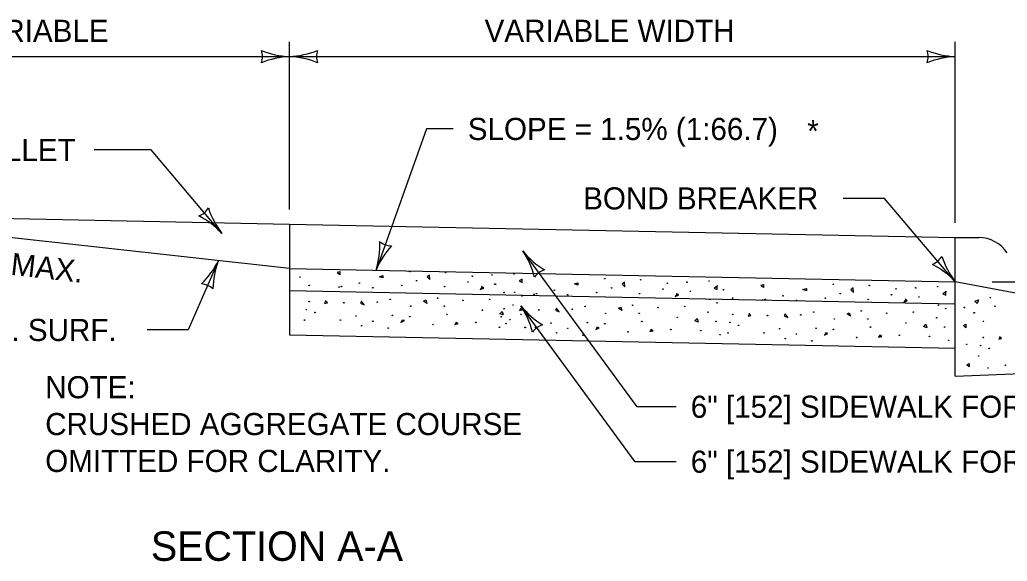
# Model space of a CAD drawing. Extents: x 49987.9 to 50021, y 49987.6 to 50011.4.
# Drawn here: x 50004.279 to 50006.956, y 50005.135 to 50006.604 of the extents above; entities that cross this region are included whole.
import ezdxf

# ---------------------------------------------------------------- set-up
doc = ezdxf.new("R2010")
doc.units = 0
for name, color, linetype in [('Level 1', 7, 'Continuous'), ('Level 2', 7, 'Continuous'), ('Level 3', 7, 'Continuous'), ('Level 4', 7, 'Continuous')]:
    doc.layers.add(name, color=color, linetype=linetype)

msp = doc.modelspace()

# ---------------------------------------------------------------- linework, layer by layer
at = {"layer": 'Level 1'}
for p, q in [((50005.0099, 50005.9293), (50002.004, 50006.2599)), ((50003.6615, 50006.0776), (50005.0099, 50006.0493)), ((50005.0099, 50006.0494), (50006.8149, 50006.0132)), ((50005.0099, 50006.0494), (50005.0099, 50005.8694)), ((50006.8149, 50005.6366), (50006.8149, 50006.0132)), ((50006.8149, 50006.0132), (50006.8787, 50006.0132)), ((50005.0099, 50005.9293), (50006.8149, 50005.8932)), ((50005.0099, 50005.9293), (50005.0099, 50005.7493)), ((50005.2536, 50005.9066), (50005.2631, 50005.9097)), ((50005.2536, 50005.9066), (50005.2631, 50005.9097)), ((50005.2631, 50005.9035), (50005.2536, 50005.9066)), ((50005.2631, 50005.9035), (50005.2536, 50005.9066)), ((50005.2631, 50005.9097), (50005.2631, 50005.9035)), ((50005.2631, 50005.9097), (50005.2631, 50005.9035)), ((50005.6408, 50005.8998), (50005.633, 50005.8952)), ((50005.6408, 50005.8913), (50005.6408, 50005.8998)), ((50005.6408, 50005.8913), (50005.6408, 50005.899)), ((50005.633, 50005.8952), (50005.6408, 50005.8913)), ((50005.633, 50005.8952), (50005.6408, 50005.8913)), ((50005.7822, 50005.8873), (50005.7917, 50005.8904)), ((50005.7822, 50005.8873), (50005.7917, 50005.8904)), ((50005.7917, 50005.8842), (50005.7822, 50005.8873)), ((50005.7917, 50005.8842), (50005.7822, 50005.8873)), ((50005.7917, 50005.8904), (50005.7917, 50005.8842)), ((50005.7917, 50005.8904), (50005.7917, 50005.8842)), ((50006.4021, 50005.8719), (50006.4116, 50005.875)), ((50006.4021, 50005.8719), (50006.4116, 50005.875)), ((50006.4116, 50005.8688), (50006.4021, 50005.8719)), ((50006.4116, 50005.8688), (50006.4021, 50005.8719)), ((50006.4116, 50005.875), (50006.4116, 50005.8688)), ((50006.4116, 50005.875), (50006.4116, 50005.8688)), ((50007.1057, 50005.8376), (50006.8149, 50005.8932)), ((50005.373, 50005.8408), (50005.3792, 50005.8438)), ((50005.373, 50005.8408), (50005.3792, 50005.8438)), ((50005.3792, 50005.8438), (50005.3823, 50005.8345)), ((50005.3792, 50005.8438), (50005.3823, 50005.8345)), ((50006.8683, 50005.8406), (50006.8777, 50005.8437)), ((50006.8683, 50005.8406), (50006.8777, 50005.8437)), ((50006.8777, 50005.8437), (50006.8745, 50005.8343)), ((50006.8777, 50005.8437), (50006.8745, 50005.8343)), ((50005.3823, 50005.8345), (50005.373, 50005.8408)), ((50005.3823, 50005.8345), (50005.373, 50005.8408)), ((50005.6367, 50005.821), (50005.6331, 50005.815)), ((50005.6331, 50005.815), (50005.6412, 50005.817)), ((50005.6412, 50005.817), (50005.6367, 50005.821)), ((50005.9016, 50005.8215), (50005.9078, 50005.8245)), ((50005.9016, 50005.8215), (50005.9078, 50005.8245)), ((50005.9109, 50005.8152), (50005.9016, 50005.8215)), ((50005.9109, 50005.8152), (50005.9016, 50005.8215)), ((50005.9078, 50005.8245), (50005.9109, 50005.8152)), ((50005.9078, 50005.8245), (50005.9109, 50005.8152)), ((50006.8745, 50005.8343), (50006.8683, 50005.8406)), ((50006.8745, 50005.8343), (50006.8683, 50005.8406)), ((50005.5799, 50005.8062), (50005.5863, 50005.8124)), ((50005.5799, 50005.8062), (50005.5863, 50005.8124)), ((50005.5894, 50005.803), (50005.5799, 50005.8062)), ((50005.5894, 50005.803), (50005.5799, 50005.8062)), ((50005.5863, 50005.8124), (50005.5894, 50005.803)), ((50005.5863, 50005.8124), (50005.5894, 50005.803)), ((50006.1085, 50005.7869), (50006.1149, 50005.7931)), ((50006.1085, 50005.7869), (50006.1149, 50005.7931)), ((50006.1149, 50005.7931), (50006.118, 50005.7837)), ((50006.1149, 50005.7931), (50006.118, 50005.7837)), ((50006.5215, 50005.8061), (50006.5277, 50005.8091)), ((50006.5215, 50005.8061), (50006.5277, 50005.8091)), ((50006.5308, 50005.7998), (50006.5215, 50005.8061)), ((50006.5308, 50005.7998), (50006.5215, 50005.8061)), ((50006.5277, 50005.8091), (50006.5308, 50005.7998)), ((50006.5277, 50005.8091), (50006.5308, 50005.7998)), ((50005.462, 50005.7829), (50005.4583, 50005.7773)), ((50005.4583, 50005.7773), (50005.4674, 50005.7794)), ((50005.4674, 50005.7794), (50005.462, 50005.7829)), ((50006.118, 50005.7837), (50006.1085, 50005.7869)), ((50006.118, 50005.7837), (50006.1085, 50005.7869)), ((50006.7284, 50005.7715), (50006.7348, 50005.7777)), ((50006.7284, 50005.7715), (50006.7348, 50005.7777)), ((50006.7379, 50005.7683), (50006.7284, 50005.7715)), ((50006.7379, 50005.7683), (50006.7284, 50005.7715)), ((50006.7348, 50005.7777), (50006.7379, 50005.7683)), ((50006.7348, 50005.7777), (50006.7379, 50005.7683)), ((50006.837, 50005.7746), (50006.8433, 50005.7778)), ((50006.837, 50005.7746), (50006.8433, 50005.7778)), ((50006.8433, 50005.7684), (50006.837, 50005.7746)), ((50006.8433, 50005.7684), (50006.837, 50005.7746)), ((50006.8433, 50005.7778), (50006.8433, 50005.7684)), ((50006.8433, 50005.7778), (50006.8433, 50005.7684)), ((50005.0099, 50005.7493), (50006.8149, 50005.7132)), ((50006.8149, 50005.6366), (50007.5685, 50005.6679)), ((50006.8464, 50005.6679), (50006.8527, 50005.6712)), ((50006.8464, 50005.6679), (50006.8527, 50005.6712)), ((50006.8527, 50005.6618), (50006.8464, 50005.6679)), ((50006.8527, 50005.6618), (50006.8464, 50005.6679)), ((50006.8527, 50005.6712), (50006.8527, 50005.6618)), ((50006.8527, 50005.6712), (50006.8527, 50005.6618))]:
    msp.add_line(p, q, dxfattribs=at)
for points in [[(50005.1396, 50005.9188), (50005.1466, 50005.9206), (50005.1466, 50005.9118), (50005.1389, 50005.9175)], [(50005.1396, 50005.9188), (50005.1466, 50005.9206), (50005.1466, 50005.9118), (50005.1389, 50005.9175)], [(50005.3892, 50005.9112), (50005.3829, 50005.9061), (50005.3904, 50005.899), (50005.3892, 50005.9112)], [(50005.3892, 50005.9112), (50005.3829, 50005.9061), (50005.3904, 50005.899), (50005.3892, 50005.9112)], [(50005.532, 50005.8797), (50005.5268, 50005.8721), (50005.5364, 50005.8759), (50005.5307, 50005.8805)], [(50005.532, 50005.8797), (50005.5268, 50005.8721), (50005.5364, 50005.8759), (50005.5307, 50005.8805)], [(50005.9178, 50005.8919), (50005.9115, 50005.8868), (50005.919, 50005.8797), (50005.9178, 50005.8919)], [(50005.9178, 50005.8919), (50005.9115, 50005.8868), (50005.919, 50005.8797), (50005.9178, 50005.8919)], [(50006.1713, 50005.8816), (50006.1616, 50005.8759), (50006.1694, 50005.872), (50006.1694, 50005.8797)], [(50006.1713, 50005.8816), (50006.1616, 50005.8759), (50006.1694, 50005.872), (50006.1694, 50005.8797)], [(50006.2881, 50005.8841), (50006.2951, 50005.8859), (50006.2951, 50005.8771), (50006.2874, 50005.8828)], [(50006.2881, 50005.8841), (50006.2951, 50005.8859), (50006.2951, 50005.8771), (50006.2874, 50005.8828)], [(50006.5377, 50005.8765), (50006.5314, 50005.8714), (50006.5389, 50005.8643), (50006.5377, 50005.8765)], [(50006.5377, 50005.8765), (50006.5314, 50005.8714), (50006.5389, 50005.8643), (50006.5377, 50005.8765)], [(50006.0606, 50005.8604), (50006.0554, 50005.8528), (50006.065, 50005.8566), (50006.0593, 50005.8612)], [(50006.0606, 50005.8604), (50006.0554, 50005.8528), (50006.065, 50005.8566), (50006.0593, 50005.8612)], [(50006.6805, 50005.845), (50006.6753, 50005.8374), (50006.6849, 50005.8412), (50006.6792, 50005.8458)], [(50006.6805, 50005.845), (50006.6753, 50005.8374), (50006.6849, 50005.8412), (50006.6792, 50005.8458)], [(50006.7912, 50005.8662), (50006.7815, 50005.8605), (50006.7893, 50005.8566), (50006.7893, 50005.8643)], [(50006.7912, 50005.8662), (50006.7815, 50005.8605), (50006.7893, 50005.8566), (50006.7893, 50005.8643)], [(50005.1088, 50005.8414), (50005.1045, 50005.8343), (50005.1126, 50005.8363), (50005.107, 50005.8414)], [(50005.1088, 50005.8414), (50005.1045, 50005.8343), (50005.1126, 50005.8363), (50005.107, 50005.8414)], [(50005.2049, 50005.8408), (50005.2024, 50005.835), (50005.2126, 50005.8305), (50005.2049, 50005.8408)], [(50005.2049, 50005.8408), (50005.2024, 50005.835), (50005.2126, 50005.8305), (50005.2049, 50005.8408)], [(50005.7335, 50005.8215), (50005.731, 50005.8157), (50005.7412, 50005.8112), (50005.7335, 50005.8215)], [(50005.7335, 50005.8215), (50005.731, 50005.8157), (50005.7412, 50005.8112), (50005.7335, 50005.8215)], [(50006.2573, 50005.8067), (50006.253, 50005.7996), (50006.2611, 50005.8016), (50006.2555, 50005.8067)], [(50006.2573, 50005.8067), (50006.253, 50005.7996), (50006.2611, 50005.8016), (50006.2555, 50005.8067)], [(50006.3534, 50005.8061), (50006.3509, 50005.8003), (50006.3611, 50005.7958), (50006.3534, 50005.8061)], [(50006.3534, 50005.8061), (50006.3509, 50005.8003), (50006.3611, 50005.7958), (50006.3534, 50005.8061)], [(50005.3144, 50005.7883), (50005.3117, 50005.7825), (50005.3213, 50005.7876), (50005.315, 50005.7889)], [(50005.3144, 50005.7883), (50005.3117, 50005.7825), (50005.3213, 50005.7876), (50005.315, 50005.7889)], [(50005.843, 50005.769), (50005.8403, 50005.7632), (50005.8499, 50005.7683), (50005.8436, 50005.7696)], [(50005.843, 50005.769), (50005.8403, 50005.7632), (50005.8499, 50005.7683), (50005.8436, 50005.7696)], [(50005.9908, 50005.7639), (50005.9869, 50005.758), (50005.996, 50005.7601), (50005.9902, 50005.7639)], [(50005.9908, 50005.7639), (50005.9869, 50005.758), (50005.996, 50005.7601), (50005.9902, 50005.7639)], [(50006.4629, 50005.7536), (50006.4602, 50005.7478), (50006.4698, 50005.7529), (50006.4635, 50005.7542)], [(50006.4629, 50005.7536), (50006.4602, 50005.7478), (50006.4698, 50005.7529), (50006.4635, 50005.7542)], [(50006.6107, 50005.7485), (50006.6068, 50005.7426), (50006.6159, 50005.7447), (50006.6101, 50005.7485)], [(50006.6107, 50005.7485), (50006.6068, 50005.7426), (50006.6159, 50005.7447), (50006.6101, 50005.7485)], [(50006.9369, 50005.744), (50006.9326, 50005.7369), (50006.9407, 50005.7389), (50006.9351, 50005.744)], [(50006.9369, 50005.744), (50006.9326, 50005.7369), (50006.9407, 50005.7389), (50006.9351, 50005.744)]]:
    msp.add_lwpolyline(points, dxfattribs=at)
for centre in [(50005.0381, 50005.9061), (50005.0381, 50005.9061), (50005.3362, 50005.9208), (50005.3362, 50005.9208), (50005.4335, 50005.9177), (50005.4335, 50005.9177), (50005.5056, 50005.9083), (50005.5056, 50005.9083), (50005.5593, 50005.9113), (50005.5593, 50005.9113), (50005.6188, 50005.9145), (50005.6188, 50005.9145), (50005.8648, 50005.9015), (50005.8648, 50005.9015), (50005.9621, 50005.8984), (50005.9621, 50005.8984), (50005.0632, 50005.8832), (50005.0632, 50005.8832), (50005.1445, 50005.8785), (50005.1445, 50005.8785), (50005.151, 50005.88), (50005.151, 50005.88), (50005.1993, 50005.8895), (50005.1993, 50005.8895), (50005.2358, 50005.8769), (50005.2358, 50005.8769), (50005.3142, 50005.8832), (50005.3142, 50005.8832), (50005.3545, 50005.8957), (50005.3545, 50005.8957), (50005.4303, 50005.88), (50005.4303, 50005.88), (50005.4936, 50005.8925), (50005.4936, 50005.8925), (50005.5667, 50005.8868), (50005.5667, 50005.8868), (50005.5684, 50005.8863), (50005.5684, 50005.8863), (50005.7279, 50005.8702), (50005.7279, 50005.8702), (50005.8831, 50005.8764), (50005.8831, 50005.8764), (50006.0222, 50005.8732), (50006.0222, 50005.8732), (50006.0342, 50005.889), (50006.0342, 50005.889), (50006.0879, 50005.892), (50006.0879, 50005.892), (50006.1474, 50005.8952), (50006.1474, 50005.8952), (50006.1866, 50005.8714), (50006.1866, 50005.8714), (50006.4847, 50005.8861), (50006.4847, 50005.8861), (50006.582, 50005.883), (50006.582, 50005.883), (50006.6541, 50005.8736), (50006.6541, 50005.8736), (50006.7078, 50005.8766), (50006.7078, 50005.8766), (50006.7673, 50005.8798), (50006.7673, 50005.8798), (50005.2828, 50005.8455), (50005.2828, 50005.8455), (50005.4115, 50005.8486), (50005.4115, 50005.8486), (50005.4805, 50005.8424), (50005.4805, 50005.8424), (50005.5527, 50005.8455), (50005.5527, 50005.8455), (50005.5918, 50005.8639), (50005.5918, 50005.8639), (50005.6206, 50005.8644), (50005.6206, 50005.8644), (50005.6406, 50005.8549), (50005.6406, 50005.8549), (50005.6731, 50005.8592), (50005.6731, 50005.8592), (50005.6796, 50005.8607), (50005.6796, 50005.8607), (50005.7644, 50005.8576), (50005.7644, 50005.8576), (50005.8428, 50005.8639), (50005.8428, 50005.8639), (50005.9589, 50005.8607), (50005.9589, 50005.8607), (50006.097, 50005.867), (50006.097, 50005.867), (50006.1492, 50005.8451), (50006.1492, 50005.8451), (50006.2117, 50005.8485), (50006.2117, 50005.8485), (50006.293, 50005.8438), (50006.293, 50005.8438), (50006.2995, 50005.8453), (50006.2995, 50005.8453), (50006.3478, 50005.8548), (50006.3478, 50005.8548), (50006.3843, 50005.8422), (50006.3843, 50005.8422), (50006.4627, 50005.8485), (50006.4627, 50005.8485), (50006.503, 50005.861), (50006.503, 50005.861), (50006.5788, 50005.8453), (50006.5788, 50005.8453), (50006.6421, 50005.8578), (50006.6421, 50005.8578), (50006.7169, 50005.8516), (50006.7169, 50005.8516), (50006.9102, 50005.8499), (50006.9102, 50005.8499), (50005.0555, 50005.8174), (50005.0555, 50005.8174), (50005.0632, 50005.8392), (50005.0632, 50005.8392), (50005.1573, 50005.8361), (50005.1573, 50005.8361), (50005.2478, 50005.8378), (50005.2478, 50005.8378), (50005.3386, 50005.8268), (50005.3386, 50005.8268), (50005.4294, 50005.8268), (50005.4294, 50005.8268), (50005.5329, 50005.8159), (50005.5329, 50005.8159), (50005.5918, 50005.8199), (50005.6159, 50005.8299), (50005.6159, 50005.8299), (50005.6859, 50005.8168), (50005.6859, 50005.8168), (50005.7764, 50005.8185), (50005.7764, 50005.8185), (50005.8114, 50005.8262), (50005.8114, 50005.8262), (50005.9401, 50005.8293), (50005.9401, 50005.8293), (50006.0091, 50005.8231), (50006.0091, 50005.8231), (50006.0813, 50005.8262), (50006.0813, 50005.8262), (50006.1692, 50005.8356), (50006.1692, 50005.8356), (50006.7691, 50005.8297), (50006.7691, 50005.8297), (50006.7891, 50005.8202), (50006.7891, 50005.8202), (50006.8398, 50005.8233), (50006.8398, 50005.8233), (50006.9226, 50005.8266), (50006.9226, 50005.8266), (50005.0506, 50005.789), (50005.0506, 50005.789), (50005.0788, 50005.8096), (50005.0788, 50005.8096), (50005.1479, 50005.789), (50005.1479, 50005.789), (50005.1901, 50005.8002), (50005.1901, 50005.8002), (50005.2891, 50005.8016), (50005.2891, 50005.8016), (50005.3362, 50005.7984), (50005.3362, 50005.7984), (50005.4366, 50005.8047), (50005.4366, 50005.8047), (50005.5841, 50005.7981), (50005.5841, 50005.7981), (50005.6074, 50005.7903), (50005.6074, 50005.7903), (50005.6374, 50005.8047), (50005.6374, 50005.8047), (50005.8672, 50005.8075), (50005.8672, 50005.8075), (50005.958, 50005.8075), (50005.958, 50005.8075), (50006.0615, 50005.7966), (50006.0615, 50005.7966), (50006.1445, 50005.8106), (50006.1445, 50005.8106), (50006.2117, 50005.8045), (50006.2117, 50005.8045), (50006.3058, 50005.8014), (50006.3058, 50005.8014), (50006.3963, 50005.8031), (50006.3963, 50005.8031), (50006.4313, 50005.8108), (50006.4313, 50005.8108), (50006.4871, 50005.7921), (50006.4871, 50005.7921), (50006.56, 50005.8139), (50006.56, 50005.8139), (50006.5779, 50005.7921), (50006.5779, 50005.7921), (50006.629, 50005.8077), (50006.629, 50005.8077), (50006.7012, 50005.8108), (50006.7012, 50005.8108), (50006.7644, 50005.7952), (50006.7644, 50005.7952), (50006.8662, 50005.8087), (50006.8662, 50005.8087), (50005.2056, 50005.7736), (50005.2056, 50005.7736), (50005.2358, 50005.7859), (50005.2358, 50005.7859), (50005.2776, 50005.7673), (50005.2776, 50005.7673), (50005.3989, 50005.7765), (50005.3989, 50005.7765), (50005.5151, 50005.7827), (50005.5151, 50005.7827), (50005.5792, 50005.7697), (50005.5792, 50005.7697), (50005.5966, 50005.7796), (50005.5966, 50005.7796), (50005.6488, 50005.7689), (50005.6488, 50005.7689), (50005.6765, 50005.7697), (50005.6765, 50005.7697), (50005.7187, 50005.7809), (50005.7187, 50005.7809), (50005.7644, 50005.7666), (50005.7644, 50005.7666), (50005.8177, 50005.7823), (50005.8177, 50005.7823), (50005.8648, 50005.7791), (50005.8648, 50005.7791), (50005.9652, 50005.7854), (50005.9652, 50005.7854), (50006.0437, 50005.7634), (50006.0437, 50005.7634), (50006.166, 50005.7854), (50006.166, 50005.7854), (50006.204, 50005.7827), (50006.204, 50005.7827), (50006.2273, 50005.7749), (50006.2273, 50005.7749), (50006.3386, 50005.7655), (50006.3386, 50005.7655), (50006.4376, 50005.7669), (50006.4376, 50005.7669), (50006.4847, 50005.7637), (50006.4847, 50005.7637), (50006.5851, 50005.77), (50006.5851, 50005.77), (50006.6814, 50005.7812), (50006.6814, 50005.7812), (50006.7859, 50005.77), (50006.7859, 50005.77), (50006.8913, 50005.7858), (50006.8913, 50005.7858), (50005.7342, 50005.7543), (50005.7342, 50005.7543), (50005.8062, 50005.748), (50005.8062, 50005.748), (50005.9275, 50005.7572), (50005.9275, 50005.7572), (50006.1252, 50005.7603), (50006.1252, 50005.7603), (50006.1774, 50005.7496), (50006.1774, 50005.7496), (50006.1991, 50005.7543), (50006.1991, 50005.7543), (50006.2964, 50005.7543), (50006.2964, 50005.7543), (50006.3541, 50005.7389), (50006.3541, 50005.7389), (50006.3843, 50005.7512), (50006.3843, 50005.7512), (50006.5474, 50005.7418), (50006.5474, 50005.7418), (50006.6636, 50005.748), (50006.6636, 50005.748), (50006.7451, 50005.7449), (50006.7451, 50005.7449), (50006.8913, 50005.7418), (50006.8913, 50005.7418), (50006.4261, 50005.7326), (50006.4261, 50005.7326), (50006.7973, 50005.7342), (50006.7973, 50005.7342), (50006.8461, 50005.7232), (50006.8461, 50005.7232), (50006.8836, 50005.72), (50006.8836, 50005.72), (50006.9069, 50005.7122), (50006.9069, 50005.7122), (50006.8787, 50005.6916), (50006.8787, 50005.6916), (50006.9038, 50005.659), (50006.9038, 50005.659), (50006.9509, 50005.6665), (50006.9509, 50005.6665)]:
    msp.add_circle(centre, 0.000763, dxfattribs=at)
msp.add_arc((50006.8778, 50005.919), 0.0941, 33.983, 89.4567, dxfattribs=at)
at = {"layer": 'Level 3'}
for p, q in [((50005.0099, 50006.0894), (50005.0099, 50006.5442)), ((50006.8149, 50006.0532), (50006.8149, 50006.5442)), ((50003.6615, 50006.5042), (50005.0099, 50006.5042)), ((50005.0099, 50006.5042), (50006.8149, 50006.5042)), ((50005.3816, 50006.3078), (50005.2449, 50005.9246)), ((50005.4533, 50006.3078), (50005.3816, 50006.3078)), ((50004.6346, 50006.2507), (50004.4802, 50006.2507)), ((50004.8266, 50006.0245), (50004.6346, 50006.2507)), ((50006.6229, 50006.1194), (50006.5112, 50006.1194)), ((50006.8149, 50005.8932), (50006.6229, 50006.1194)), ((50004.8172, 50005.9505), (50004.7353, 50005.7623)), ((50005.9522, 50005.5539), (50005.6426, 50005.9767)), ((50006.9149, 50005.8932), (50007.1843, 50005.8932)), ((50005.9469, 50005.4048), (50005.6373, 50005.8276)), ((50004.7353, 50005.7623), (50004.6237, 50005.7623)), ((50006.0578, 50005.5539), (50005.9522, 50005.5539)), ((50006.0578, 50005.4048), (50005.9469, 50005.4048))]:
    msp.add_line(p, q, dxfattribs=at)
for centre, radius, start, end in [((50005.019, 50006.7263), 0.2223, 247.456, 267.6395), ((50004.8817, 50006.5042), 0.0548, 342.1388, 17.8612), ((50004.9984, 50006.7369), 0.233, 272.8273, 292.0772), ((50005.1381, 50006.5042), 0.0548, 162.1388, 197.8612), ((50006.824, 50006.7263), 0.2223, 247.456, 267.6395), ((50006.6867, 50006.5042), 0.0548, 342.1388, 17.8612), ((50005.0214, 50006.2715), 0.233, 92.8273, 112.0772), ((50005.0007, 50006.2821), 0.2223, 67.456, 87.6395), ((50006.8264, 50006.2715), 0.233, 92.8273, 112.0772), ((50004.7436, 50006.1222), 0.0548, 292.464, 328.1863), ((50005.0114, 50006.1663), 0.233, 198.248, 217.4978), ((50004.6631, 50005.8738), 0.2223, 42.6856, 62.8691), ((50005.0218, 50005.992), 0.233, 343.1886, 2.4385), ((50005.451, 50005.8413), 0.2223, 137.8173, 158.0008), ((50005.288, 50006.0453), 0.0548, 232.5001, 268.2225), ((50004.6172, 50006.0475), 0.2223, 313.945, 334.1285), ((50005.0352, 50005.8682), 0.233, 159.3163, 178.5662), ((50005.4579, 50005.8528), 0.2223, 13.6699, 33.8534), ((50005.8235, 50006.1234), 0.233, 219.0412, 238.291), ((50006.7319, 50005.9909), 0.0548, 292.464, 328.1863), ((50006.9997, 50006.035), 0.233, 198.248, 217.4978), ((50005.7183, 50005.8732), 0.0548, 108.3527, 144.075), ((50006.6514, 50005.7425), 0.2223, 42.6856, 62.8691), ((50004.7661, 50005.8329), 0.0548, 48.6278, 84.3502), ((50005.4526, 50005.7038), 0.2223, 13.653, 33.8365), ((50005.8183, 50005.9743), 0.233, 219.0243, 238.2742), ((50005.713, 50005.7241), 0.0548, 108.3358, 144.0582)]:
    msp.add_arc(centre, radius, start, end, dxfattribs=at)
at = {"layer": 'Level 4'}
msp.add_line((50005.0099, 50005.8694), (50006.8149, 50005.8334), dxfattribs=at)

# ---------------------------------------------------------------- texts
at = {"layer": 'Level 2'}
for s, height, p in [('VARIABLE', 0.06, (50004.1271, 50006.5442)), ('VARIABLE WIDTH', 0.06, (50005.5389, 50006.5442)), ('SLOPE = 1.5% (1:66.7)', 0.06, (50005.4933, 50006.2778)), ('*', 0.06, (50006.4137, 50006.2721)), ('FILLET', 0.06, (50004.1671, 50006.2207)), ('BOND BREAKER', 0.06, (50005.8061, 50006.0894)), ('APP. SURF.', 0.06, (50004.0955, 50005.7323)), ('NOTE:', 0.06, (50004.3477, 50005.5769)), ('6" [152] SIDEWALK FOR RAMP', 0.06, (50006.0978, 50005.5239)), ('CRUSHED AGGREGATE COURSE', 0.06, (50004.3477, 50005.4769)), ('OMITTED FOR CLARITY.', 0.06, (50004.3477, 50005.3769)), ('6" [152] SIDEWALK FOR APPROACH', 0.06, (50006.0978, 50005.3748)), ('SECTION A-A', 0.08, (50004.6341, 50005.1357))]:
    msp.add_text(s, height=height, dxfattribs=at).set_placement(p)
msp.add_text('10% (1:10) MAX.', height=0.06, rotation=353.5455, dxfattribs=at).set_placement((50003.84, 50005.9588))

doc.saveas('drawing.dxf')
